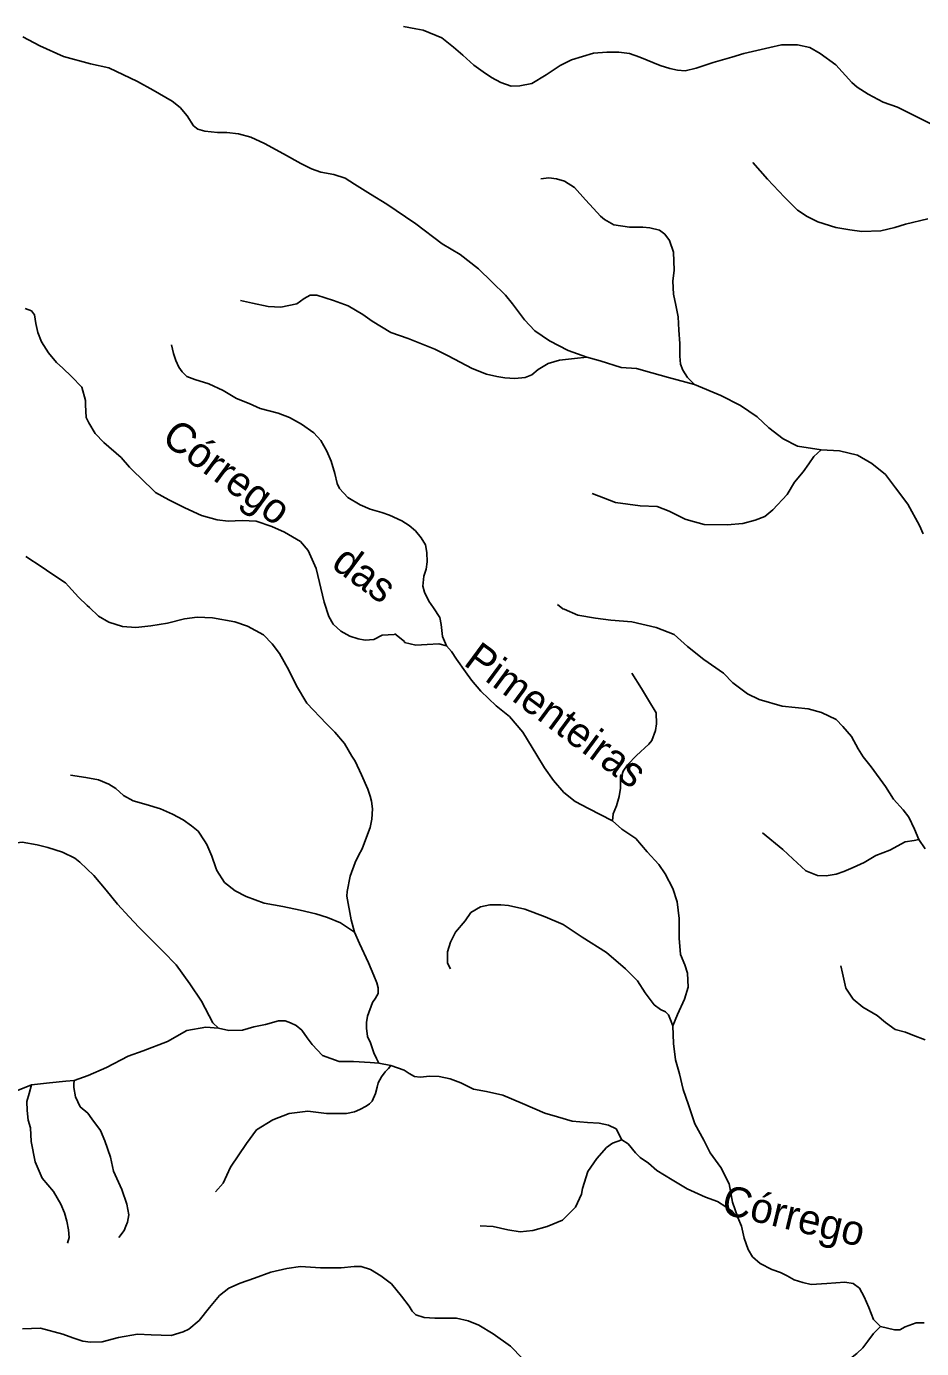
# Model space of a CAD drawing. Extents: x 436.3 to 500.4, y 8231 to 8286.4.
# Drawn here: x 472.02 to 478.01, y 8257.73 to 8266.57 of the extents above; entities that cross this region are included whole.
import ezdxf
from ezdxf.enums import TextEntityAlignment as Align

# ---------------------------------------------------------------- set-up
doc = ezdxf.new("R2010")
doc.units = 0
doc.header["$LTSCALE"] = 0.08
doc.linetypes.add('LONG_DASHED', pattern=[7.5, 6, -1.5])
doc.layers.add('61', color=7, linetype='Continuous')
doc.layers.add('9', color=7, linetype='LONG_DASHED', lineweight=25)

msp = doc.modelspace()

# ---------------------------------------------------------------- linework, layer by layer
at = {"layer": '9'}
for points in [[(474.5447, 8266.5734), (474.6277, 8266.5563), (474.6762, 8266.5494), (474.8006, 8266.4977), (474.8801, 8266.4357), (474.9424, 8266.3806), (475.0151, 8266.3151), (475.0773, 8266.2703), (475.1327, 8266.2324), (475.195, 8266.1978), (475.2642, 8266.1738), (475.323, 8266.1772), (475.4026, 8266.191), (475.4995, 8266.2497), (475.593, 8266.3119), (475.6138, 8266.3223), (475.6692, 8266.3499), (475.8146, 8266.3948), (475.9046, 8266.4017), (475.9843, 8266.4018), (476.057, 8266.3914), (476.1262, 8266.3674), (476.2613, 8266.3122), (476.3253, 8266.2914), (476.3773, 8266.281), (476.4292, 8266.2776), (476.502, 8266.2949), (476.6163, 8266.3329), (476.7411, 8266.3675), (476.8208, 8266.3916), (476.9939, 8266.4331), (477.0721, 8266.4506), (477.1796, 8266.4506), (477.2627, 8266.4334), (477.332, 8266.392), (477.436, 8266.3162), (477.5435, 8266.199), (477.5781, 8266.168), (477.6509, 8266.1198), (477.7514, 8266.0681), (477.8485, 8266.0336), (478.098, 8265.9096)], [(471.9999, 8266.5036), (472.1129, 8266.4438), (472.2717, 8266.3734), (472.4518, 8266.3242), (472.5754, 8266.296), (472.766, 8266.2045), (472.872, 8266.1482), (472.9991, 8266.0742), (473.0522, 8266.032), (473.098, 8265.9755), (473.1404, 8265.9086), (473.1701, 8265.8863), (473.216, 8265.8722), (473.3008, 8265.8652), (473.3645, 8265.8653), (473.4422, 8265.8547), (473.5235, 8265.8336), (473.6153, 8265.7913), (473.7426, 8265.7209), (473.8592, 8265.6575), (473.9299, 8265.6223), (473.9918, 8265.6), (474.0802, 8265.5824), (474.1545, 8265.5578), (474.2181, 8265.5189), (474.3242, 8265.452), (474.4338, 8265.3851), (474.5577, 8265.3005), (474.6284, 8265.2546), (474.8029, 8265.1193), (474.9232, 8265.0489), (475.047, 8264.9537), (475.1356, 8264.8656), (475.2276, 8264.7774), (475.2736, 8264.7175), (475.355, 8264.6117), (475.4223, 8264.5378), (475.5214, 8264.4708), (475.6453, 8264.4074), (475.7708, 8264.3631)], [(476.8808, 8265.664), (476.978, 8265.5511), (477.0916, 8265.4318), (477.1791, 8265.3448), (477.244, 8265.3029), (477.3154, 8265.2675), (477.4354, 8265.2288), (477.5295, 8265.2128), (477.6106, 8265.2032), (477.737, 8265.2065), (477.8312, 8265.2291), (477.9024, 8265.2518), (478.0516, 8265.2873)], [(475.4633, 8265.5548), (475.5158, 8265.5601), (475.5681, 8265.5548), (475.6206, 8265.5392), (475.6888, 8265.4975), (475.7623, 8265.4139), (475.8147, 8265.3565), (475.862, 8265.3043), (475.8882, 8265.2834), (475.9511, 8265.2468), (476.0561, 8265.2312), (476.1454, 8265.2312), (476.1926, 8265.2261), (476.2556, 8265.2104), (476.2923, 8265.1844), (476.3238, 8265.1426), (476.35, 8265.0642), (476.3553, 8264.9441), (476.3448, 8264.8709), (476.35, 8264.7822), (476.3658, 8264.709), (476.3815, 8264.6306), (476.3867, 8264.5419), (476.392, 8264.4531), (476.3922, 8264.3681), (476.3975, 8264.3158), (476.4133, 8264.2741), (476.4447, 8264.2271), (476.49, 8264.1802)], [(473.4544, 8264.7398), (473.5344, 8264.722), (473.6412, 8264.6999), (473.7258, 8264.6954), (473.8327, 8264.7177), (473.8816, 8264.7532), (473.9217, 8264.7755), (473.9662, 8264.7755), (474.0775, 8264.74), (474.1754, 8264.7044), (474.2734, 8264.6468), (474.3357, 8264.6025), (474.4604, 8264.527), (474.5762, 8264.4871), (474.7544, 8264.4161), (474.8435, 8264.3718), (475.0043, 8264.287), (475.101, 8264.2477), (475.1681, 8264.2319), (475.2215, 8264.2241), (475.2905, 8264.2202), (475.3576, 8264.2261), (475.4031, 8264.2438), (475.4465, 8264.2793), (475.5117, 8264.3187), (475.5887, 8264.3423), (475.6895, 8264.3541), (475.7708, 8264.3631)], [(472.0151, 8264.6881), (472.0575, 8264.6712), (472.0788, 8264.6458), (472.0872, 8264.5865), (472.1, 8264.5271), (472.1255, 8264.4636), (472.1721, 8264.3916), (472.224, 8264.3262), (472.2664, 8264.2881), (472.3258, 8264.233), (472.3938, 8264.161), (472.4192, 8264.0719), (472.4192, 8264.0423), (472.4235, 8263.9575), (472.4405, 8263.9236), (472.4829, 8263.8515), (472.5424, 8263.7922), (472.6571, 8263.6905), (472.7122, 8263.6269), (472.7335, 8263.6057), (472.8694, 8263.4743), (472.8864, 8263.4573), (472.9772, 8263.4088), (473.0834, 8263.3537), (473.1938, 8263.3028), (473.3001, 8263.2732), (473.3722, 8263.2647), (473.4658, 8263.2689), (473.5593, 8263.2647), (473.6655, 8263.2307), (473.7505, 8263.1926), (473.8568, 8263.129), (473.9078, 8263.0697), (473.9604, 8262.9492), (474.0156, 8262.7244), (474.0454, 8262.6269), (474.0752, 8262.576), (474.1262, 8262.5294), (474.1857, 8262.4954), (474.241, 8262.4786), (474.2877, 8262.4701), (474.3472, 8262.4743), (474.4025, 8262.5039), (474.4834, 8262.5082), (474.4876, 8262.5124), (474.5514, 8262.4616), (474.5514, 8262.4531), (474.6279, 8262.4361), (474.7044, 8262.4403), (474.781, 8262.4447), (474.8321, 8262.4319)], [(472.9937, 8264.4444), (473.0067, 8264.3871), (473.0234, 8264.3391), (473.0438, 8264.2947), (473.0659, 8264.2632), (473.0974, 8264.2337), (473.1493, 8264.2133), (473.2438, 8264.1838), (473.3402, 8264.1395), (473.429, 8264.0859), (473.5125, 8264.0527), (473.5859, 8264.0184), (473.7064, 8263.987), (473.7823, 8263.9575), (473.8639, 8263.913), (473.9454, 8263.8557), (473.9918, 8263.804), (474.0326, 8263.7337), (474.0604, 8263.6672), (474.0849, 8263.5848), (474.1016, 8263.5183), (474.1164, 8263.4831), (474.1739, 8263.4239), (474.2555, 8263.374), (474.3223, 8263.3463), (474.4002, 8263.3223), (474.4521, 8263.3056), (474.5336, 8263.2687), (474.5838, 8263.2372), (474.6246, 8263.2003), (474.6623, 8263.1529), (474.6919, 8263.1066), (474.7012, 8263.0567), (474.703, 8262.9938), (474.6956, 8262.944), (474.6808, 8262.8977), (474.6752, 8262.8311), (474.6864, 8262.7905), (474.7142, 8262.7313), (474.7457, 8262.6869), (474.7875, 8262.6217), (474.797, 8262.5743), (474.8066, 8262.4952), (474.8321, 8262.4319)], [(475.7708, 8264.3631), (475.8594, 8264.3384), (476.001, 8264.2927), (476.1038, 8264.2858), (476.2065, 8264.2576), (476.3163, 8264.2259), (476.49, 8264.1802)], [(476.49, 8264.1802), (476.6672, 8264.1063), (476.7983, 8264.0394), (476.9098, 8263.9636), (476.9878, 8263.8896), (477.0834, 8263.8156), (477.1791, 8263.7664), (477.3387, 8263.7419)], [(475.8056, 8263.45), (475.8812, 8263.4217), (475.963, 8263.3904), (476.1268, 8263.3687), (476.2401, 8263.3625), (476.322, 8263.3312), (476.4291, 8263.278), (476.4512, 8263.2717), (476.5551, 8263.2436), (476.7096, 8263.2406), (476.8135, 8263.2502), (476.8954, 8263.2721), (476.9616, 8263.2974), (477.0152, 8263.3412), (477.1098, 8263.4448), (477.1602, 8263.5263), (477.217, 8263.5954), (477.2548, 8263.6488), (477.2895, 8263.6989), (477.3387, 8263.7419)], [(477.3387, 8263.7419), (477.4593, 8263.7349), (477.5798, 8263.7069), (477.6756, 8263.6505), (477.7677, 8263.5766), (477.8351, 8263.4886), (477.9166, 8263.3793), (477.9956, 8263.2372), (478.0204, 8263.1808)], [(472.0204, 8263.0302), (472.1282, 8262.9579), (472.1874, 8262.9177), (472.2846, 8262.8539), (472.3059, 8262.8302), (472.3732, 8262.7582), (472.43, 8262.7014), (472.4466, 8262.6872), (472.5059, 8262.6304), (472.5746, 8262.5902), (472.667, 8262.5618), (472.7547, 8262.5548), (472.8565, 8262.5666), (472.9679, 8262.5832), (473.0817, 8262.6116), (473.1658, 8262.6235), (473.2677, 8262.6187), (473.417, 8262.5928), (473.5024, 8262.5643), (473.6091, 8262.5052), (473.666, 8262.4461), (473.7159, 8262.3798), (473.7775, 8262.2687), (473.8297, 8262.1645), (473.8993, 8262.0493), (474.0298, 8261.9097), (474.0868, 8261.8553), (474.1508, 8261.7796), (474.2006, 8261.6944), (474.222, 8261.6613), (474.2648, 8261.5696), (474.3076, 8261.4726), (474.3218, 8261.4277), (474.3313, 8261.3922), (474.3385, 8261.3425), (474.3337, 8261.2739), (474.3219, 8261.2171), (474.2911, 8261.1344), (474.2698, 8261.0753), (474.2438, 8261.0303), (474.2224, 8260.9831), (474.1894, 8260.8917), (474.168, 8260.79), (474.1658, 8260.7569), (474.1943, 8260.6008), (474.218, 8260.5166)], [(475.5744, 8262.7076), (475.6102, 8262.6792), (475.6196, 8262.6768), (475.71, 8262.6366), (475.8289, 8262.6177), (475.9313, 8262.6036), (476.0716, 8262.5918), (476.2334, 8262.5541), (476.3547, 8262.5068), (476.4428, 8262.4264), (476.5522, 8262.3412), (476.6855, 8262.2488), (476.746, 8262.1839), (476.8459, 8262.1105), (476.9221, 8262.0727), (477.0776, 8262.0273), (477.2515, 8262.0109), (477.3396, 8261.985), (477.4371, 8261.9401), (477.4824, 8261.8928), (477.5395, 8261.8265), (477.5847, 8261.7436), (477.618, 8261.6893), (477.6728, 8261.6229), (477.7684, 8261.4917), (477.8209, 8261.4065), (477.8851, 8261.3355), (477.9232, 8261.2858), (477.9613, 8261.2053), (477.9899, 8261.1367)], [(474.8321, 8262.4319), (474.8661, 8262.3937), (474.9001, 8262.3429), (474.9597, 8262.2581), (474.9992, 8262.2012), (475.0629, 8262.1292), (475.1651, 8262.0317), (475.2544, 8261.9596), (475.3438, 8261.8537), (475.4373, 8261.701), (475.4884, 8261.6162), (475.548, 8261.5315), (475.6161, 8261.4509), (475.6927, 8261.3915), (475.7821, 8261.3449), (475.9416, 8261.2607)], [(476.0722, 8262.2489), (476.1357, 8262.1476), (476.1833, 8262.0686), (476.2341, 8261.9832), (476.2373, 8261.9105), (476.231, 8261.8662), (476.2055, 8261.7997), (476.1864, 8261.7744), (476.1038, 8261.6984), (476.0434, 8261.6351), (476.0148, 8261.5929), (475.9957, 8261.5359), (475.9956, 8261.479), (475.9861, 8261.4252), (475.9703, 8261.3619), (475.948, 8261.3082), (475.9416, 8261.2607)], [(472.3182, 8261.566), (472.4218, 8261.5521), (472.5055, 8261.5362), (472.5752, 8261.5063), (472.6211, 8261.4785), (472.6728, 8261.4308), (472.7366, 8261.3951), (472.8243, 8261.3711), (472.9199, 8261.3414), (473.0016, 8261.3056), (473.0714, 8261.2678), (473.1272, 8261.228), (473.1731, 8261.1922), (473.215, 8261.1286), (473.2309, 8261.1028), (473.2636, 8261.0245), (473.2896, 8260.9469), (473.2976, 8260.929), (473.3494, 8260.8494), (473.4192, 8260.7937), (473.4931, 8260.756), (473.6146, 8260.7102), (473.7374, 8260.6878), (473.855, 8260.6639), (473.9588, 8260.64), (474.0365, 8260.6142), (474.1242, 8260.5803), (474.1781, 8260.5445), (474.218, 8260.5166)], [(475.9416, 8261.2607), (476.0046, 8261.207), (476.0983, 8261.1435), (476.1749, 8261.0545), (476.2516, 8260.9698), (476.2941, 8260.9062), (476.3454, 8260.8087), (476.3751, 8260.7198), (476.388, 8260.6096), (476.3881, 8260.4781), (476.3966, 8260.3681), (476.4269, 8260.2979), (476.444, 8260.2429), (476.4484, 8260.1497), (476.4229, 8260.0691), (476.3762, 8259.9674), (476.3464, 8259.8912)], [(476.9452, 8261.1816), (477.0804, 8261.0707), (477.148, 8261.0065), (477.2361, 8260.9277), (477.3125, 8260.8957), (477.3713, 8260.8929), (477.4389, 8260.9046), (477.4889, 8260.9223), (477.5505, 8260.9486), (477.624, 8260.9838), (477.7033, 8261.0307), (477.7974, 8261.0659), (477.9002, 8261.1216), (477.959, 8261.1305), (477.9899, 8261.1367)], [(471.449, 8260.8715), (471.5456, 8260.9416), (471.6086, 8260.9814), (471.8392, 8261.0888), (471.9023, 8261.1087), (471.9953, 8261.1188), (472.095, 8261.1021), (472.1681, 8261.0823), (472.2644, 8261.0525), (472.3475, 8261.0127), (472.3808, 8260.9862), (472.4738, 8260.8966), (472.5569, 8260.7972), (472.6335, 8260.7044), (472.7114, 8260.62), (472.7746, 8260.5504), (472.851, 8260.4741), (472.9375, 8260.3879), (473.0241, 8260.2984), (473.1173, 8260.1724), (473.1938, 8260.0563), (473.2711, 8259.9108), (473.3091, 8259.8764)], [(477.9899, 8261.1367), (478.0328, 8261.0753)], [(474.8596, 8260.2718), (474.8383, 8260.31), (474.8383, 8260.3862), (474.8594, 8260.4497), (474.8934, 8260.5176), (474.9571, 8260.5938), (474.9954, 8260.6489), (475.0591, 8260.687), (475.1229, 8260.6996), (475.1953, 8260.6996), (475.2463, 8260.6954), (475.3569, 8260.67), (475.493, 8260.6192), (475.6122, 8260.5683), (475.7399, 8260.4836), (475.9016, 8260.3819), (476.0295, 8260.2718), (476.1104, 8260.1913), (476.1617, 8260.1109), (476.2214, 8260.0305), (476.264, 8260.0008), (476.2971, 8259.9849), (476.316, 8259.9645), (476.3303, 8259.9315), (476.3464, 8259.8912)], [(474.218, 8260.5166), (474.2514, 8260.4425), (474.3108, 8260.3125), (474.3467, 8260.228), (474.3658, 8260.1783), (474.3753, 8260.1453), (474.3753, 8260.1074), (474.3587, 8260.0767), (474.3374, 8260.046), (474.3043, 8259.9562), (474.2973, 8259.9137), (474.2973, 8259.8758), (474.3045, 8259.8192), (474.3236, 8259.7766), (474.3473, 8259.7105), (474.364, 8259.6727), (474.3809, 8259.6417)], [(477.4697, 8260.2916), (477.4794, 8260.2432), (477.5023, 8260.1435), (477.5509, 8260.0696), (477.6157, 8260.0149), (477.713, 8259.9603), (477.7681, 8259.9121), (477.833, 8259.8672), (477.9011, 8259.848), (477.9497, 8259.8287), (478.034, 8259.7967)], [(472.344, 8259.525), (472.4374, 8259.5592), (472.5597, 8259.6127), (472.7049, 8259.6889), (472.8043, 8259.7232), (472.9667, 8259.7862), (473.0966, 8259.8587), (473.2229, 8259.8815), (473.3091, 8259.8764)], [(473.3091, 8259.8764), (473.3782, 8259.8592), (473.4681, 8259.8626), (473.5441, 8259.8832), (473.6235, 8259.9005), (473.7099, 8259.9245), (473.7548, 8259.9244), (473.7893, 8259.9107), (473.8274, 8259.8935), (473.8654, 8259.8625), (473.9001, 8259.8107), (473.9347, 8259.7659), (474.0039, 8259.6936), (474.1146, 8259.6522), (474.2115, 8259.6521), (474.322, 8259.6452), (474.3809, 8259.6417), (474.4612, 8259.625)], [(476.3464, 8259.8912), (476.3509, 8259.7726), (476.3639, 8259.6626), (476.3896, 8259.5695), (476.4154, 8259.465), (476.4496, 8259.3634), (476.4926, 8259.2365), (476.5524, 8259.1265), (476.5952, 8259.0419), (476.6678, 8258.9447), (476.7235, 8258.8347), (476.7451, 8258.712), (476.7805, 8258.6091)], [(473.2883, 8258.7803), (473.3383, 8258.8385), (473.3882, 8258.9466), (473.4964, 8259.1045), (473.563, 8259.1959), (473.6714, 8259.2625), (473.7798, 8259.304), (473.9049, 8259.3205), (474.0302, 8259.3039), (474.1637, 8259.3038), (474.2177, 8259.3156), (474.2536, 8259.3309), (474.2947, 8259.3539), (474.3177, 8259.3692), (474.3357, 8259.3871), (474.3587, 8259.4383), (474.369, 8259.4818), (474.3766, 8259.5099), (474.3971, 8259.5508), (474.4228, 8259.5841), (474.4458, 8259.6046), (474.4612, 8259.625)], [(474.4612, 8259.625), (474.5503, 8259.5934), (474.5834, 8259.5719), (474.618, 8259.5511), (474.656, 8259.5477), (474.7217, 8259.5546), (474.784, 8259.5511), (474.8566, 8259.5373), (474.9294, 8259.5097), (475.0124, 8259.4683), (475.099, 8259.451), (475.2098, 8259.427), (475.3414, 8259.3718), (475.4904, 8259.3063), (475.5753, 8259.2816), (475.6724, 8259.2541), (475.7762, 8259.2438), (475.8524, 8259.2403), (475.9149, 8259.2266), (475.9669, 8259.2025), (476.004, 8259.1294)], [(472.0588, 8259.4972), (472.1775, 8259.5095), (472.2883, 8259.521), (472.344, 8259.525)], [(472.6419, 8258.4765), (472.677, 8258.5232), (472.6886, 8258.5504), (472.7004, 8258.5777), (472.7081, 8258.6282), (472.6963, 8258.6983), (472.661, 8258.7956), (472.6062, 8258.9201), (472.5866, 8259.0135), (472.5475, 8259.1224), (472.52, 8259.1904), (472.4614, 8259.2682), (472.434, 8259.3071), (472.3833, 8259.3499), (472.352, 8259.416), (472.3402, 8259.4783), (472.3402, 8259.5017), (472.344, 8259.525)], [(471.7656, 8259.3008), (471.8481, 8259.3608), (471.9023, 8259.4103), (471.965, 8259.4581), (472.0588, 8259.4972)], [(472.2981, 8258.4373), (472.3097, 8258.4762), (472.3057, 8258.5268), (472.294, 8258.5851), (472.2782, 8258.6396), (472.2548, 8258.6979), (472.204, 8258.7835), (472.1297, 8258.873), (472.0828, 8258.9819), (472.0554, 8259.1181), (472.0514, 8259.2092), (472.0357, 8259.2598), (472.0279, 8259.3259), (472.0278, 8259.3843), (472.0433, 8259.4388), (472.0588, 8259.4972)], [(475.0578, 8258.5543), (475.1455, 8258.5497), (475.2426, 8258.5267), (475.3258, 8258.513), (475.4088, 8258.5222), (475.5058, 8258.5497), (475.6074, 8258.591), (475.6949, 8258.6783), (475.7363, 8258.7656), (475.7409, 8258.8023), (475.7776, 8258.9172), (475.8374, 8259.0044), (475.902, 8259.078), (475.9435, 8259.1055), (476.004, 8259.1294)], [(476.004, 8259.1294), (476.0467, 8259.1027), (476.0954, 8259.0408), (476.1267, 8259.0098), (476.1823, 8258.972), (476.2378, 8258.9238), (476.3419, 8258.8619), (476.4426, 8258.8), (476.5641, 8258.745), (476.645, 8258.7157), (476.7005, 8258.6812), (476.7457, 8258.6503), (476.7805, 8258.6091)], [(476.7805, 8258.6091), (476.8049, 8258.5506), (476.8224, 8258.4714), (476.8504, 8258.3956), (476.8781, 8258.3474), (476.9303, 8258.3027), (477.0067, 8258.2614), (477.0657, 8258.2408), (477.1108, 8258.2203), (477.156, 8258.1927), (477.215, 8258.1756), (477.2705, 8258.1618), (477.3745, 8258.1688), (477.4958, 8258.1759), (477.5522, 8258.1679), (477.5928, 8258.1367), (477.6246, 8258.0785), (477.6563, 8258.0068), (477.688, 8257.9263), (477.7333, 8257.8816)], [(471.998, 8257.866), (472.1186, 8257.8702), (472.2684, 8257.8287), (472.3349, 8257.8039), (472.4016, 8257.7832), (472.4515, 8257.7749), (472.5305, 8257.779), (472.6386, 8257.808), (472.7676, 8257.8288), (472.8591, 8257.8247), (472.9924, 8257.8205), (473.0714, 8257.8454), (473.1089, 8257.8619), (473.1781, 8257.9214), (473.2487, 8258.0084), (473.3151, 8258.0872), (473.3775, 8258.137), (473.4535, 8258.1699), (473.5492, 8258.2031), (473.6574, 8258.2445), (473.7657, 8258.2694), (473.8572, 8258.2818), (473.9905, 8258.2735), (474.1279, 8258.2735), (474.2154, 8258.2817), (474.2612, 8258.2817), (474.3237, 8258.2609), (474.3946, 8258.2194), (474.4656, 8258.1655), (474.5324, 8258.0825), (474.5826, 8258.0161), (474.6035, 8257.9829), (474.6285, 8257.958), (474.6828, 8257.9414), (474.7536, 8257.9372), (474.8995, 8257.9372), (474.9768, 8257.9192), (475.0478, 8257.8902), (475.1438, 8257.8321), (475.2608, 8257.7491), (475.3402, 8257.6662)], [(477.2414, 8257.6515), (477.2792, 8257.6666), (477.3377, 8257.6666), (477.4087, 8257.6583), (477.4713, 8257.6541), (477.5089, 8257.6583), (477.5339, 8257.6666), (477.5756, 8257.6999), (477.6172, 8257.7372), (477.6506, 8257.7829), (477.6881, 8257.8328), (477.7333, 8257.8816)], [(477.7333, 8257.8816), (477.828, 8257.8592), (477.864, 8257.8593), (477.9001, 8257.8773), (477.9721, 8257.9042), (478.0262, 8257.9043)]]:
    msp.add_lwpolyline(points, dxfattribs=at)

# ---------------------------------------------------------------- texts
at = {"layer": '61'}
for s, rotation, p in [('Córrego      das         Pimenteiras', 323.559, (474.4966, 8262.6352)), ('Córrego          das   Pimenteiras', 346.559, (478.4981, 8258.1985))]:
    msp.add_text(s, height=0.2, rotation=rotation, dxfattribs=at).set_placement(p, align=Align.CENTER)

doc.saveas('drawing.dxf')
